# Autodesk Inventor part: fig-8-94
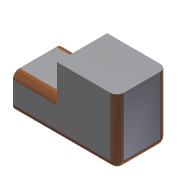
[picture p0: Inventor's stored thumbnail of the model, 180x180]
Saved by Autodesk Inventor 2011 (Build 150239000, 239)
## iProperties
Shininess: 64.0
Length Units: 11269
Angle Units: 11279
Time Units: 11290
Mass Units: 11283
Length Display Precision: 3
Angle Display Precision: 2
Compacted: True
Part Number: fig-8-94
Document SubType Name: Modeling
Created: 2002-12
Designer: deepak
Density: 1 g/cm^3
Density: 0.0
Volumn: 0.0
Area: 0.0
PropertySet Name: Model Information
Control State: 0
Master: False
Checked Out: False
Author: deepak
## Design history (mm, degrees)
sketch "Sketch1"
  geometry: L1 (-26.972, 23.346)-(8.906, 23.346); L2 (8.906, 23.346)-(8.906, 5.025); L3 (8.906, -15.84)-(-26.972, -15.84); L4 (-26.972, -15.84)-(-26.972, 23.346); L5 (8.906, -15.84)-(35.369, -15.84); L6 (35.369, -15.84)-(35.369, 5.025); L7 (35.369, 5.025)-(8.906, 5.025)
  constraints: 14 end point, 3 parallel, 2 horizontal, 2 perpendicular
extrude "Extrusion1" new body sketch "Sketch1" stored distance "d0" = 30; taper "d1" = 0 deg
fillet "Fillet1" dims "d2" = 4, "d3" = 4
delete_face "Delete Face1"
delete_face "Delete Face2"
delete_face "Delete Face3"
body "Solid1"
